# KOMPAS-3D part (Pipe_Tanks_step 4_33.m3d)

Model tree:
1. X Axis
2. Y Axis
3. Z Axis  (labels: Transfer Dy 50-150; Pipe Dn 50; Valve Dy 50)
     Òîëùèíà ñòåíêè 1 = 1

Referenced files in C:\Documents and Settings\kashirsky\Мои документы\Camtasia Studio\Pipelines3D\Tanks\: Tanks_step 4.a3d
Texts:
  Pipe Dn 50
  Steel ASTM A295
  Three Point Plane
  Plane at Angle
  Line and Point Plane
  Axis through Two Vertices
  Axis of Feature
  Axis of Conical Surface
  Axis through Edge
  Trim by Surface
  Trim by Sketch
  Feature with No History
  Intersection Axis of Two Planes
  Two Line Plane
  Line and Face Plane
  Bend by line
  Hole in sheet body
  Cut in sheet body
  Point in CM
  Linear Dimension from Line to Point
  Surface Finish Symbol
  Geometric Tolerance Symbol
  Leader #1
  Leader #2
  Leader #3
  Shape Deviations and Datum
  Node point number
  Mark of coordination axis
  Node point designation
  Mark/Reference designation with leader
  Mark/reference designation on line
  Mark/Reference designation without leader
  Transfer Dy 50-150
  Valve Dy 50
  Plane of section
